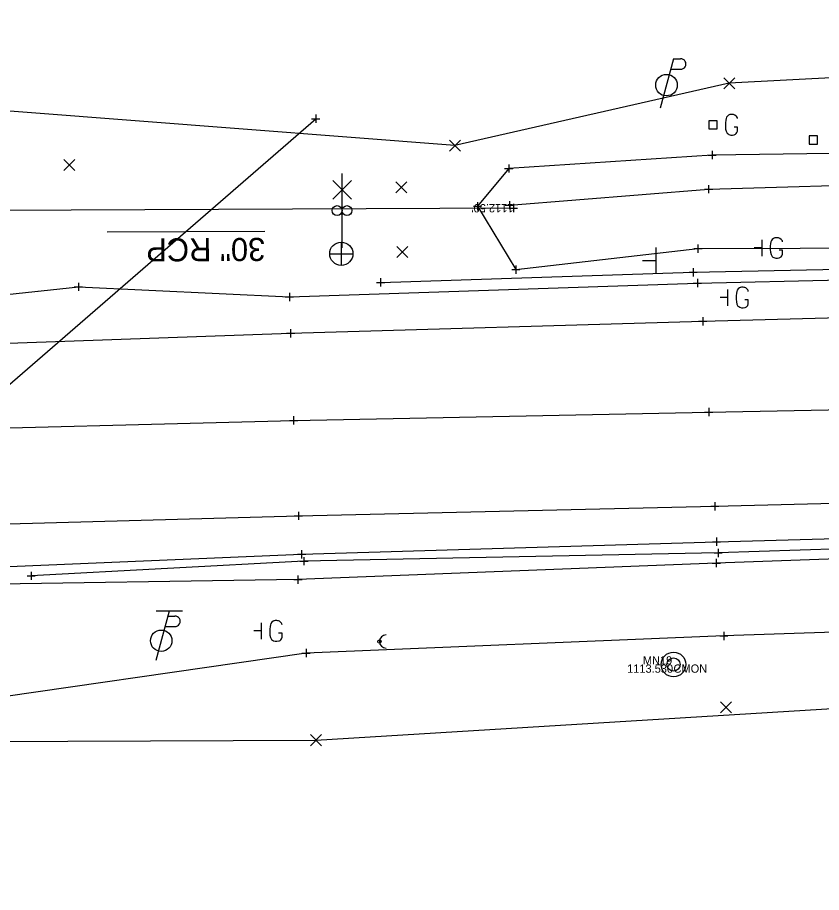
# Model space of a CAD drawing. Extents: x 2402028 to 2407435, y 498611 to 499105.
# Drawn here: x 2403055.5 to 2403153, y 498611.7 to 498717.9 of the extents above; entities that cross this region are included whole.
import ezdxf

# ---------------------------------------------------------------- set-up
doc = ezdxf.new("R2010")
doc.units = 0
for name, color, linetype in [('_CIVIL_CONSTRUCTION', 7, 'Continuous'), ('DR_X_Ditch', 7, 'Continuous'), ('DR_X_Storm_Sewer', 7, 'Continuous'), ('DR_X_Text', 7, 'Continuous'), ('PV_X_COP', 7, 'Continuous'), ('PV_X_EOP', 7, 'Continuous'), ('PV_X_Shoulder', 7, 'Continuous'), ('RD_X_GR_Lt', 7, 'Continuous'), ('RD_X_RR_1', 7, 'Continuous'), ('RW_X_CL_1000_Stations', 7, 'Continuous'), ('RW_X_CL_100_Bearings', 7, 'Continuous'), ('RW_X_CL_100_Cardinal_Points', 7, 'Continuous'), ('RW_X_CL_100_Distances', 7, 'Continuous'), ('RW_X_CL_100_Stations', 7, 'Continuous'), ('RW_X_CL_500_Bearings', 7, 'Continuous'), ('RW_X_CL_500_Cardinal_Points', 7, 'Continuous'), ('RW_X_CL_500_Distances', 7, 'Continuous'), ('RW_X_CL_500_Stations', 7, 'Continuous'), ('RW_X_Esmt_RR', 7, 'Continuous'), ('RW_X_Esmt_SH', 7, 'Continuous'), ('RW_X_Parent_Tract_Area', 7, 'Continuous'), ('SC_Scratch1', 7, 'Continuous'), ('SV_X_Break_Lines', 7, 'Continuous'), ('SV_X_Terrain_Boundary', 7, 'Continuous')]:
    doc.layers.add(name, color=color, linetype=linetype)

msp = doc.modelspace()

# ---------------------------------------------------------------- linework, layer by layer
at = {"layer": 'DR_X_Ditch'}
msp.add_lwpolyline([(2403115.12, 498695.09), (2403139.28, 498697.03), (2403188.69, 498698.47), (2403237.26, 498698.52), (2403287.58, 498700.04), (2403338.31, 498701.02), (2403388.05, 498703.88), (2403439.2, 498702.19), (2403487.16, 498703.92), (2403540.55, 498705.7), (2403586.78, 498706.71), (2403636.91, 498706.23), (2403686.46, 498707.34), (2403736.22, 498708.05), (2403785.8, 498709.01), (2403836.25, 498710.7), (2403885.81, 498712.33), (2403935.71, 498713.55), (2403984.74, 498715.92), (2404035.79, 498716.24), (2404057.73, 498716.67)], dxfattribs=at)
at = {"layer": 'DR_X_Storm_Sewer'}
msp.add_line((2403115.62, 498694.73), (2403040.17, 498694.38), dxfattribs=at)
at = {"layer": 'DR_X_Text'}
msp.add_line((2403066.36, 498691.85), (2403085.45, 498691.94), dxfattribs=at)
at = {"layer": 'PV_X_COP'}
msp.add_lwpolyline([(2402290.78, 498650.6), (2402340.95, 498651.54), (2402390.57, 498652.34), (2402439.7, 498652.49), (2402489.93, 498654.64), (2402539.81, 498655.53), (2402589.95, 498657.15), (2402640.38, 498659.77), (2402689.17, 498658.83), (2402739.11, 498659.65), (2402789.43, 498660.95), (2402839.82, 498661.75), (2402889.36, 498663.57), (2402939.81, 498664.58), (2402990.03, 498665.92), (2403038.83, 498667.68), (2403088.96, 498668.97), (2403139.3, 498669.99), (2403188.98, 498670.93), (2403236.78, 498672.43), (2403288.95, 498673.92), (2403339.4, 498675.07), (2403388.6, 498676.54)], dxfattribs=at)
at = {"layer": 'PV_X_EOP'}
for points in [[(2402289.63, 498661.52), (2402339.86, 498662.34), (2402390.35, 498663.57), (2402439.38, 498664.47), (2402489.03, 498665.67), (2402538.63, 498666.7), (2402622.2, 498668.45), (2402639.44, 498668.97), (2402688.21, 498669.91), (2402738.3, 498670.77), (2402784.26, 498671.54), (2402839.07, 498673.4), (2402887.81, 498674.54), (2402939.07, 498675.44), (2402989.96, 498676.81), (2403039.49, 498677.82), (2403088.59, 498679.54), (2403138.58, 498681), (2403188.48, 498682.36), (2403236.31, 498683.8), (2403287.8, 498685.14), (2403338.61, 498686.54), (2403387.34, 498688.53)], [(2402290.91, 498639.29), (2402341.07, 498640.3), (2402390.61, 498641.23), (2402440.65, 498642.38), (2402490.15, 498643.23), (2402540.35, 498644.45), (2402590.8, 498645.77), (2402640.33, 498646.73), (2402690.18, 498647.64), (2402739.92, 498648.63), (2402790, 498649.56), (2402840.05, 498650.65), (2402889.89, 498651.78), (2402940.17, 498653.2), (2402989.78, 498654.87), (2403039.63, 498656.02), (2403089.54, 498657.39), (2403140.04, 498658.56), (2403189.82, 498659.81), (2403238.57, 498661.04), (2403289.76, 498662.62), (2403340.13, 498663.91), (2403389.07, 498665.43)]]:
    msp.add_lwpolyline(points, dxfattribs=at)
at = {"layer": 'PV_X_Shoulder'}
for p, q in [((2403137.93, 498685.64), (2403186.2, 498686.67)), ((2403034.53, 498682.16), (2403062.85, 498685.18)), ((2403062.85, 498685.18), (2403088.44, 498683.95)), ((2403088.44, 498683.95), (2403137.93, 498685.64))]:
    msp.add_line(p, q, dxfattribs=at)
msp.add_lwpolyline([(2402291.13, 498635.58), (2402341.06, 498636.96), (2402390.62, 498637.69), (2402440.73, 498638.55), (2402490.3, 498639.85), (2402540.78, 498641.01), (2402590.73, 498641.96), (2402640.23, 498642.72), (2402690.38, 498643.95), (2402740.06, 498644.93), (2402790, 498645.7), (2402840.23, 498646.8), (2402889.99, 498648.42), (2402940.22, 498649.59), (2402989.85, 498649.92), (2403040.06, 498650.63), (2403089.93, 498652.73), (2403140.24, 498654.26), (2403189.57, 498655.62), (2403238.67, 498657.76), (2403289.89, 498659.04), (2403340.12, 498659.5), (2403389.1, 498660.69)], dxfattribs=at)
at = {"layer": 'RD_X_GR_Lt'}
for points in [[(2403099.5, 498685.71), (2403137.41, 498686.94), (2403186.56, 498687.97), (2403235.13, 498689.39), (2403253.26, 498690.33)], [(2403206.01, 498655.41), (2403190.17, 498654.52), (2403140.45, 498652.89), (2403090.21, 498651.89), (2403057.13, 498650.12)]]:
    msp.add_lwpolyline(points, dxfattribs=at)
at = {"layer": 'RD_X_RR_1'}
msp.add_lwpolyline([(2403009.49, 498634.34), (2403091.64, 498705.57)], dxfattribs=at)
at = {"layer": 'RW_X_CL_1000_Stations'}
for p, q in [((2403132.87, 498689.95), (2403132.87, 498686.75)), ((2403132.87, 498688.35), (2403131.27, 498688.35))]:
    msp.add_line(p, q, dxfattribs=at)
at = {"layer": 'RW_X_CL_100_Distances'}
for p, q in [((2403145.77, 498688.89), (2403145.77, 498690.89)), ((2403145.77, 498689.89), (2403144.82, 498689.89)), ((2403141.63, 498682.87), (2403141.63, 498684.87)), ((2403141.63, 498683.87), (2403140.68, 498683.87)), ((2403085.07, 498642.43), (2403085.07, 498644.43)), ((2403085.07, 498643.43), (2403084.12, 498643.43))]:
    msp.add_line(p, q, dxfattribs=at)
for points in [[(2403142.8, 498705.6), (2403142.78, 498705.69), (2403142.72, 498705.79), (2403142.62, 498705.89), (2403142.48, 498706.01), (2403142.38, 498706.05), (2403142.31, 498706.07), (2403142.19, 498706.09), (2403141.95, 498706.09), (2403141.85, 498706.07), (2403141.79, 498706.05), (2403141.71, 498706.01), (2403141.56, 498705.89), (2403141.46, 498705.75), (2403141.4, 498705.6), (2403141.36, 498705.38), (2403141.32, 498705.06), (2403141.32, 498704.65), (2403141.34, 498704.32), (2403141.42, 498704.06), (2403141.54, 498703.82), (2403141.64, 498703.75), (2403141.75, 498703.67), (2403141.97, 498703.59), (2403142.19, 498703.59), (2403142.4, 498703.63), (2403142.48, 498703.67), (2403142.56, 498703.71), (2403142.64, 498703.78), (2403142.72, 498703.9), (2403142.8, 498704.08), (2403142.8, 498704.57), (2403142.38, 498704.57)], [(2403139.33, 498704.33), (2403140.33, 498704.33), (2403140.33, 498705.33), (2403139.33, 498705.33), (2403139.33, 498704.33)], [(2403151.48, 498702.5), (2403152.48, 498702.5), (2403152.48, 498703.5), (2403151.48, 498703.5), (2403151.48, 498702.5)], [(2403148.25, 498690.65), (2403148.23, 498690.74), (2403148.17, 498690.84), (2403148.07, 498690.94), (2403147.93, 498691.06), (2403147.83, 498691.1), (2403147.75, 498691.12), (2403147.64, 498691.14), (2403147.4, 498691.14), (2403147.3, 498691.12), (2403147.24, 498691.1), (2403147.16, 498691.06), (2403147.01, 498690.94), (2403146.91, 498690.8), (2403146.85, 498690.65), (2403146.81, 498690.43), (2403146.77, 498690.11), (2403146.77, 498689.7), (2403146.79, 498689.37), (2403146.87, 498689.11), (2403146.99, 498688.87), (2403147.08, 498688.79), (2403147.2, 498688.72), (2403147.42, 498688.64), (2403147.64, 498688.64), (2403147.85, 498688.68), (2403147.93, 498688.72), (2403148.01, 498688.76), (2403148.09, 498688.83), (2403148.17, 498688.95), (2403148.25, 498689.13), (2403148.25, 498689.62), (2403147.83, 498689.62)], [(2403144.1, 498684.63), (2403144.08, 498684.72), (2403144.03, 498684.82), (2403143.93, 498684.92), (2403143.79, 498685.04), (2403143.69, 498685.08), (2403143.61, 498685.1), (2403143.49, 498685.12), (2403143.26, 498685.12), (2403143.16, 498685.1), (2403143.1, 498685.08), (2403143.02, 498685.04), (2403142.86, 498684.92), (2403142.77, 498684.78), (2403142.71, 498684.63), (2403142.67, 498684.41), (2403142.63, 498684.09), (2403142.63, 498683.68), (2403142.65, 498683.35), (2403142.73, 498683.09), (2403142.84, 498682.85), (2403142.94, 498682.78), (2403143.06, 498682.7), (2403143.28, 498682.62), (2403143.49, 498682.62), (2403143.71, 498682.66), (2403143.79, 498682.7), (2403143.87, 498682.74), (2403143.95, 498682.82), (2403144.03, 498682.93), (2403144.1, 498683.11), (2403144.1, 498683.6), (2403143.69, 498683.6)], [(2403087.55, 498644.18), (2403087.53, 498644.28), (2403087.47, 498644.38), (2403087.37, 498644.48), (2403087.24, 498644.6), (2403087.14, 498644.64), (2403087.06, 498644.66), (2403086.94, 498644.68), (2403086.7, 498644.68), (2403086.61, 498644.66), (2403086.55, 498644.64), (2403086.47, 498644.6), (2403086.31, 498644.48), (2403086.21, 498644.34), (2403086.15, 498644.18), (2403086.11, 498643.97), (2403086.07, 498643.65), (2403086.07, 498643.24), (2403086.09, 498642.9), (2403086.17, 498642.65), (2403086.29, 498642.41), (2403086.39, 498642.33), (2403086.51, 498642.25), (2403086.72, 498642.18), (2403086.94, 498642.18), (2403087.16, 498642.21), (2403087.24, 498642.25), (2403087.31, 498642.29), (2403087.39, 498642.37), (2403087.47, 498642.49), (2403087.55, 498642.67), (2403087.55, 498643.16), (2403087.14, 498643.16)]]:
    msp.add_lwpolyline(points, dxfattribs=at)
at = {"layer": 'RW_X_CL_100_Stations'}
for radius in [1.5, 0.8]:
    msp.add_circle((2403135.03, 498639.36), radius, dxfattribs=at)
at = {"layer": 'RW_X_CL_500_Bearings'}
for p, q in [((2403091.64, 498706.07), (2403091.64, 498705.07)), ((2403091.14, 498705.57), (2403092.14, 498705.57)), ((2403091.64, 498705.57), (2403091.64, 498705.57)), ((2403139.72, 498701.67), (2403139.72, 498700.67)), ((2403139.22, 498701.17), (2403140.22, 498701.17)), ((2403139.72, 498701.17), (2403139.72, 498701.17)), ((2403114.54, 498699.53), (2403115.54, 498699.53)), ((2403115.04, 498700.03), (2403115.04, 498699.03)), ((2403115.04, 498699.53), (2403115.04, 498699.53)), ((2403139.28, 498697.53), (2403139.28, 498696.53)), ((2403138.78, 498697.03), (2403139.78, 498697.03)), ((2403139.28, 498697.03), (2403139.28, 498697.03)), ((2403111.26, 498695.45), (2403111.26, 498694.45)), ((2403115.12, 498695.59), (2403115.12, 498694.59)), ((2403110.76, 498694.95), (2403111.76, 498694.95)), ((2403111.26, 498694.95), (2403111.26, 498694.95)), ((2403114.62, 498695.09), (2403115.62, 498695.09)), ((2403115.12, 498695.09), (2403115.12, 498695.09)), ((2403137.99, 498690.31), (2403137.99, 498689.31)), ((2403137.49, 498689.81), (2403138.49, 498689.81)), ((2403137.99, 498689.81), (2403137.99, 498689.81)), ((2403115.41, 498687.27), (2403116.41, 498687.27)), ((2403115.91, 498687.77), (2403115.91, 498686.77)), ((2403115.91, 498687.27), (2403115.91, 498687.27)), ((2403136.91, 498686.94), (2403137.91, 498686.94)), ((2403137.41, 498687.44), (2403137.41, 498686.44)), ((2403137.41, 498686.94), (2403137.41, 498686.94)), ((2403099, 498685.71), (2403100, 498685.71)), ((2403099.5, 498686.21), (2403099.5, 498685.21)), ((2403099.5, 498685.71), (2403099.5, 498685.71)), ((2403137.93, 498686.14), (2403137.93, 498685.14)), ((2403062.35, 498685.18), (2403063.35, 498685.18)), ((2403062.85, 498685.68), (2403062.85, 498684.68)), ((2403062.85, 498685.18), (2403062.85, 498685.18)), ((2403137.43, 498685.64), (2403138.43, 498685.64)), ((2403137.93, 498685.64), (2403137.93, 498685.64)), ((2403087.94, 498683.95), (2403088.94, 498683.95)), ((2403088.44, 498684.45), (2403088.44, 498683.45)), ((2403088.44, 498683.95), (2403088.44, 498683.95)), ((2403138.58, 498681.5), (2403138.58, 498680.5)), ((2403138.08, 498681), (2403139.08, 498681)), ((2403138.58, 498681), (2403138.58, 498681)), ((2403088.09, 498679.54), (2403089.09, 498679.54)), ((2403088.59, 498680.04), (2403088.59, 498679.04)), ((2403088.59, 498679.54), (2403088.59, 498679.54)), ((2403138.8, 498669.99), (2403139.8, 498669.99)), ((2403139.3, 498670.49), (2403139.3, 498669.49)), ((2403139.3, 498669.99), (2403139.3, 498669.99)), ((2403088.46, 498668.97), (2403089.46, 498668.97)), ((2403088.96, 498669.47), (2403088.96, 498668.47)), ((2403088.96, 498668.97), (2403088.96, 498668.97)), ((2403139.54, 498658.56), (2403140.54, 498658.56)), ((2403140.04, 498659.06), (2403140.04, 498658.06)), ((2403140.04, 498658.56), (2403140.04, 498658.56)), ((2403089.04, 498657.39), (2403090.04, 498657.39)), ((2403089.54, 498657.89), (2403089.54, 498656.89)), ((2403089.54, 498657.39), (2403089.54, 498657.39)), ((2403139.74, 498654.26), (2403140.74, 498654.26)), ((2403140.24, 498654.76), (2403140.24, 498653.76)), ((2403140.24, 498654.26), (2403140.24, 498654.26)), ((2403089.93, 498653.23), (2403089.93, 498652.23)), ((2403139.95, 498652.89), (2403140.95, 498652.89)), ((2403140.45, 498653.39), (2403140.45, 498652.39)), ((2403140.45, 498652.89), (2403140.45, 498652.89)), ((2403089.43, 498652.73), (2403090.43, 498652.73)), ((2403089.71, 498651.89), (2403090.71, 498651.89)), ((2403089.93, 498652.73), (2403089.93, 498652.73)), ((2403090.21, 498652.39), (2403090.21, 498651.39)), ((2403090.21, 498651.89), (2403090.21, 498651.89)), ((2403140.22, 498652.16), (2403140.22, 498651.16)), ((2403139.72, 498651.66), (2403140.72, 498651.66)), ((2403140.22, 498651.66), (2403140.22, 498651.66)), ((2403056.63, 498650.12), (2403057.63, 498650.12)), ((2403057.13, 498650.62), (2403057.13, 498649.62)), ((2403057.13, 498650.12), (2403057.13, 498650.12)), ((2403088.98, 498649.66), (2403089.98, 498649.66)), ((2403089.48, 498650.16), (2403089.48, 498649.16)), ((2403089.48, 498649.66), (2403089.48, 498649.66)), ((2403141.13, 498643.32), (2403141.13, 498642.32)), ((2403140.63, 498642.82), (2403141.63, 498642.82)), ((2403141.13, 498642.82), (2403141.13, 498642.82)), ((2403090.47, 498641.24), (2403090.47, 498640.24)), ((2403089.97, 498640.74), (2403090.97, 498640.74)), ((2403090.47, 498640.74), (2403090.47, 498640.74))]:
    msp.add_line(p, q, dxfattribs=at)
at = {"layer": 'RW_X_CL_500_Cardinal_Points'}
for p, q in [((2403073.87, 498645.84), (2403072.26, 498639.84)), ((2403075.47, 498645.84), (2403072.27, 498645.84)), ((2403073.71, 498645.24), (2403074.56, 498645.24)), ((2403073.37, 498643.96), (2403074.56, 498643.96))]:
    msp.add_line(p, q, dxfattribs=at)
for centre, radius in [((2403072.9, 498642.24), 1.3), ((2403099.37, 498642.14), 0.2)]:
    msp.add_circle(centre, radius, dxfattribs=at)
for centre, radius, start, end in [((2403074.57, 498644.6), 0.638, 268.8767, 91.1233), ((2403100.17, 498642.14), 0.8, 90, 270)]:
    msp.add_arc(centre, radius, start, end, dxfattribs=at)
at = {"layer": 'RW_X_CL_500_Distances'}
for p, q in [((2403115.12, 498694.73), (2403116.12, 498694.73)), ((2403115.62, 498695.23), (2403115.62, 498694.23)), ((2403115.62, 498694.73), (2403115.62, 498694.73))]:
    msp.add_line(p, q, dxfattribs=at)
at = {"layer": 'RW_X_CL_500_Stations'}
for p, q in [((2403141.12, 498709.2), (2403142.45, 498710.54)), ((2403141.12, 498710.54), (2403142.45, 498709.2)), ((2403107.86, 498701.64), (2403109.19, 498702.98)), ((2403107.86, 498702.98), (2403109.19, 498701.64)), ((2403061.09, 498699.31), (2403062.42, 498700.64)), ((2403061.09, 498700.64), (2403062.42, 498699.31)), ((2403101.35, 498696.57), (2403102.68, 498697.9)), ((2403101.35, 498697.9), (2403102.68, 498696.57)), ((2403101.49, 498688.75), (2403102.82, 498690.09)), ((2403101.49, 498690.09), (2403102.82, 498688.75)), ((2403140.74, 498633.48), (2403142.07, 498634.81)), ((2403140.74, 498634.81), (2403142.07, 498633.48)), ((2403090.99, 498629.51), (2403092.32, 498630.85)), ((2403090.99, 498630.85), (2403092.32, 498629.51))]:
    msp.add_line(p, q, dxfattribs=at)
at = {"layer": 'RW_X_Esmt_RR'}
for p, q in [((2403094.83, 498689.93), (2403094.83, 498698.93)), ((2403095.96, 498695.8), (2403093.7, 498698.06)), ((2403093.7, 498695.8), (2403095.96, 498698.06))]:
    msp.add_line(p, q, dxfattribs=at)
for centre in [(2403094.23, 498694.43), (2403095.43, 498694.43)]:
    msp.add_circle(centre, 0.6, dxfattribs=at)
at = {"layer": 'RW_X_Esmt_SH'}
for p, q in [((2403135.03, 498712.85), (2403133.43, 498706.85)), ((2403135.03, 498712.85), (2403135.88, 498712.85)), ((2403134.69, 498711.57), (2403135.88, 498711.57))]:
    msp.add_line(p, q, dxfattribs=at)
msp.add_circle((2403134.18, 498709.65), 1.3, dxfattribs=at)
msp.add_arc((2403135.9, 498712.21), 0.638, 268.8767, 91.1233, dxfattribs=at)
at = {"layer": 'RW_X_Parent_Tract_Area'}
for p, q in [((2403094.74, 498690.6), (2403094.74, 498687.78)), ((2403093.33, 498689.19), (2403096.15, 498689.19))]:
    msp.add_line(p, q, dxfattribs=at)
msp.add_circle((2403094.74, 498689.19), 1.41, dxfattribs=at)
at = {"layer": 'SV_X_Break_Lines'}
for points in [[(2403387.81, 498709.86), (2403338.45, 498707.66), (2403290.57, 498705.42), (2403237.15, 498702.26), (2403188.58, 498701.85), (2403139.72, 498701.17), (2403115.04, 498699.53), (2403111.26, 498694.95), (2403115.91, 498687.27), (2403137.99, 498689.81), (2403187.61, 498689.98), (2403236.19, 498690.76), (2403288.37, 498691.2), (2403337.63, 498692.95), (2403385.67, 498694.88)], [(2403326.04, 498656.48), (2403290.07, 498656.88), (2403238.78, 498655.67), (2403189.96, 498653.45), (2403140.22, 498651.66), (2403089.48, 498649.66), (2403047.99, 498649.01), (2403037.72, 498641.31)], [(2403325.44, 498652.67), (2403290.46, 498651.22), (2403239.36, 498647.62), (2403189.92, 498644.45), (2403141.13, 498642.82), (2403090.47, 498640.74), (2403045.59, 498634.26)]]:
    msp.add_lwpolyline(points, dxfattribs=at)
at = {"layer": 'SV_X_Terrain_Boundary'}
for points in [[(2403390.54, 498717.85), (2403340.67, 498716.01), (2403291.04, 498712.96), (2403238.44, 498711.46), (2403188.93, 498712.35), (2403141.78, 498709.87), (2403108.52, 498702.31), (2403030.94, 498708.33), (2402991.96, 498712.04), (2402946.72, 498714.63), (2402886.9, 498701.35), (2402808.26, 498712.11), (2402805.63, 498711.55), (2402802.55, 498713.98), (2402800.83, 498712.58), (2402791.73, 498715.48), (2402739.88, 498694.44), (2402686.71, 498702.37), (2402636.92, 498697.87)], [(2402641.3, 498620.88), (2402692.24, 498622.71), (2402740.26, 498624.67), (2402793.66, 498636.1), (2402843.48, 498611.7), (2402939.98, 498632.65), (2402988.61, 498630.24), (2403041.47, 498629.99), (2403091.65, 498630.18), (2403191.21, 498636.27), (2403240.26, 498637.09), (2403290.41, 498638.6), (2403346.11, 498636.26), (2403438.36, 498646.02)]]:
    msp.add_lwpolyline(points, dxfattribs=at)

# ---------------------------------------------------------------- texts
at = {"layer": '_CIVIL_CONSTRUCTION'}
msp.add_text('MN19', height=1, dxfattribs=at).set_placement((2403131.31, 498639.36))
at = {"layer": 'DR_X_Text'}
msp.add_text('30" RCP', height=2.8, rotation=180.2665, dxfattribs=at).set_placement((2403085.51, 498691.12))
at = {"layer": 'RW_X_CL_100_Bearings'}
msp.add_text('1113.530', height=1, dxfattribs=at).set_placement((2403129.4, 498638.36))
at = {"layer": 'RW_X_CL_100_Cardinal_Points'}
msp.add_text('CMON', height=1, dxfattribs=at).set_placement((2403135.03, 498638.36))
at = {"layer": 'SC_Scratch1'}
msp.add_text("1112.50'", height=1, rotation=180.2665, dxfattribs=at).set_placement((2403115.62, 498695.23))

doc.saveas('drawing.dxf')
